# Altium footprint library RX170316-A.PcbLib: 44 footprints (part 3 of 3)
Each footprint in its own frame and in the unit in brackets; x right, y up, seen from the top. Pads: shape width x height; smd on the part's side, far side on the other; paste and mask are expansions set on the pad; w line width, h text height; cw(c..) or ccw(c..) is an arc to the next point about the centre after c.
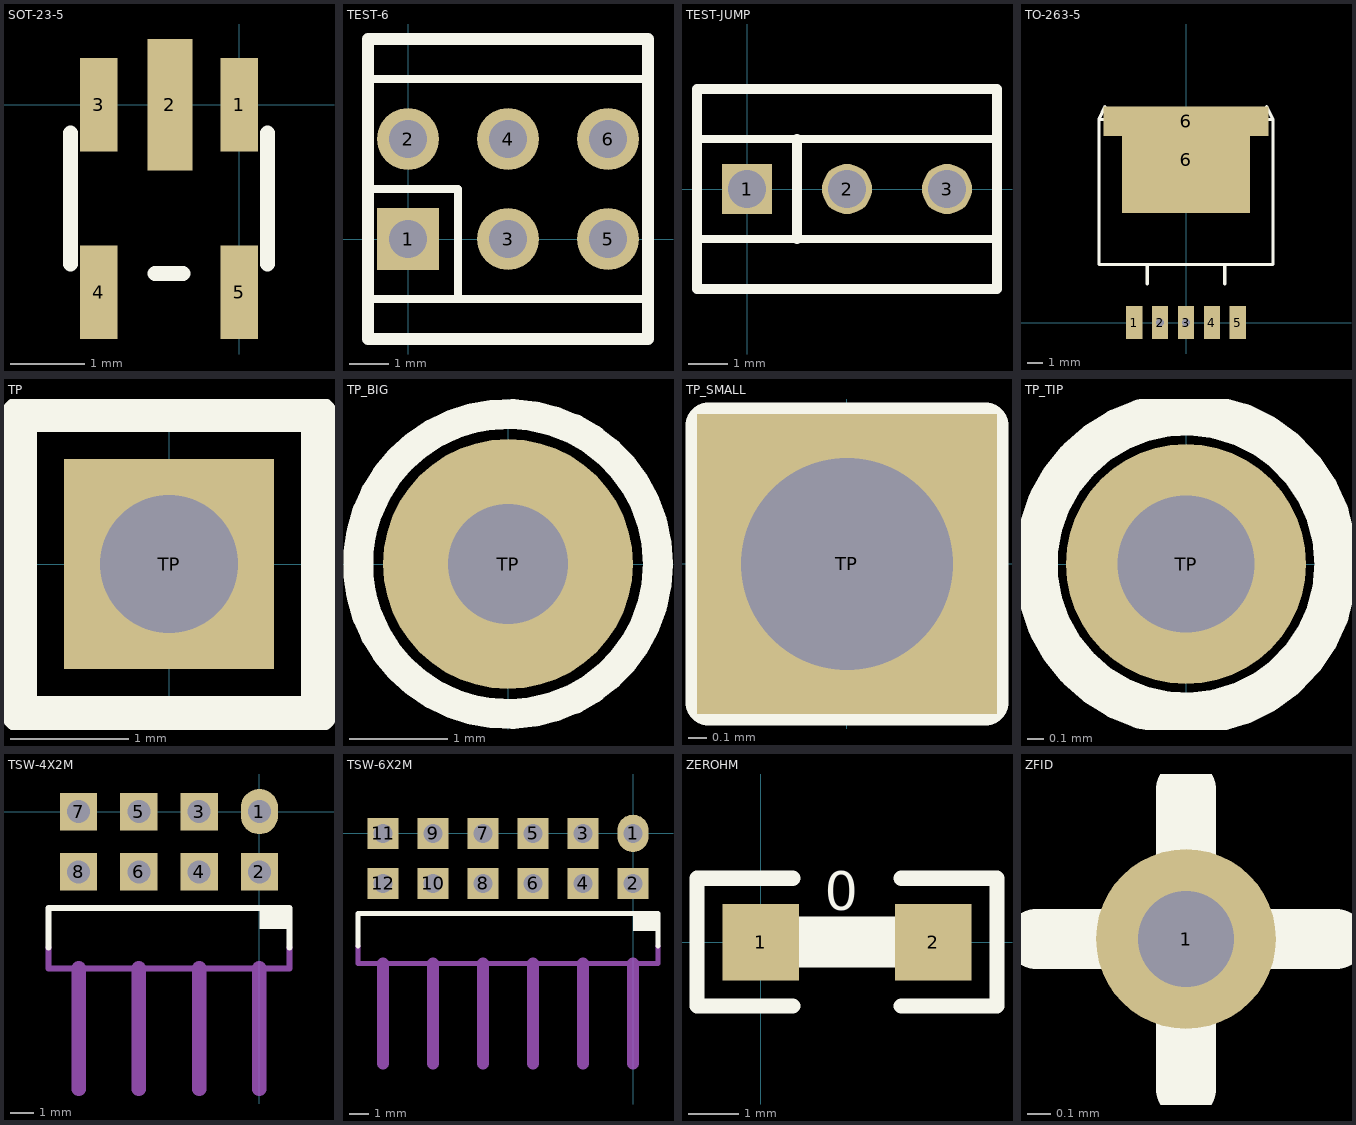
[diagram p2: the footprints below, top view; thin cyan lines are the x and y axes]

## SOT-23-5 [mil]
pads (5):
  rect 20x50 smd mask+5: 1(0,0) 3(-75,0) 4(-75,-100) 5(0,-100)
  rect 24x70 smd mask+5: 2(-37,0)
Top Overlay:
  lines w8: -90,-85 -90,-15 ; -45,-90 -30,-90 ; 15,-85 15,-15

## TEST-6 [mil]
pads (6):
  rect 62x62 hole 38: 1(0,0)
  round 62 hole 38: 2(0,100) 3(100,0) 4(100,100) 5(200,0) 6(200,100)
Top Overlay:
  lines w8: -40,-60 240,-60 ; -40,50 50,50 50,-60 ; -40,160 240,160
  lines w12: -40,-100 240,-100 240,200 -40,200 -40,-100
Mechanical 3:
  text "609-1331-ND" at -130,35 h40

## TEST-JUMP [mil]
pads (3):
  rect 50x50 hole 38: 1(0,0)
  round 50 hole 38: 2(100,0) 3(200,0)
Top Overlay:
  lines w8: -50,-50 250,-50 ; -50,50 250,50
  lines w10: 50,-50 50,50 ; -50,-100 -50,100 250,100 250,-100 -50,-100

## TO-263-5 [mil]
pads (7):
  rect 42x85 smd: 1(-134,0) 4(67,0) 5(134,0)
  rect 42x85 hole 20: 2(-67,0) 3(0,0)
  rect 330x275 smd: 6(0,420)
  rect 425x75 smd: 6(0,520)
Top Overlay:
  lines w8: -209,558 -225,525 ; -100,100 -100,150 ; 100,100 100,150 ; 208,558 225,525 ; -225,525 -225,150 225,150 225,525 ; -225,525 225,525
Top Paste:
  rectangle: -17,-40 18,40
  rectangle: 115,-40 150,40
  rectangle: 50,-40 85,40
  rectangle: -85,-40 -50,40
  rectangle: -150,-40 -115,40

## TP [mil]
pads (1):
  rect 70x70 hole 46 mask+5: TP(0,0)
Top Overlay:
  lines w12: -50,-50 -50,50 50,50 50,-50 -50,-50

## TP_BIG [mil]
pads (1):
  round 100 hole 48: TP(0,0)
Top Overlay:
  circle w12: c0,0 r60

## TP_SMALL [mil]
pads (1):
  rect 65x65 hole 46 mask+5: TP(0,0)
Top Overlay:
  lines w10: -30,-30 -30,30 30,30 30,-30 -30,-30

## TP_TIP [mil]
pads (1):
  round 56 hole 32 mask+3: TP(0,0)
Top Overlay:
  circle w10: c0,0 r35

## TSW-4X2M [mil]
pads (8):
  oval 62x75 hole 38: 1(0,0)
  rect 62x62 hole 38: 2(0,-100) 3(-100,0) 4(-100,-100) 5(-200,0) 6(-200,-100) 7(-300,0) 8(-300,-100)
Top Overlay:
  region: 0,-155 0,-195 50,-195 50,-155
  lines w10: -350,-225 -350,-160 50,-160 50,-225
Mechanical 1:
  lines w10: -350,-225 -350,-260 50,-260 50,-225
  lines w24: -300,-460 -300,-260 ; -200,-460 -200,-260 ; -100,-460 -100,-260 ; 0,-460 0,-260
  text "TSW-4X2M" at -350,-225 h50

## TSW-6X2M [mil]
pads (12):
  oval 62x75 hole 38: 1(0,0)
  rect 62x62 hole 38: 2(0,-100) 3(-100,0) 4(-100,-100) 5(-200,0) 6(-200,-100) 7(-300,0) 8(-300,-100) 9(-400,0) 10(-400,-100) 11(-500,0) 12(-500,-100)
Top Overlay:
  region: 0,-155 0,-195 50,-195 50,-155
  lines w10: -550,-225 -550,-160 50,-160 50,-225
Mechanical 1:
  lines w10: -550,-225 -550,-260 50,-260 50,-225
  lines w24: -500,-460 -500,-260 ; -400,-460 -400,-260 ; -300,-460 -300,-260 ; -200,-460 -200,-260 ; -100,-460 -100,-260 ; 0,-460 0,-260
  text "TSW-6X2M" at -445,-230 h50

## ZEROHM [mil]
pads (2):
  rect 60x60 smd: 1(0,0) 2(135,0)
Top Overlay:
  region: 30,20 30,-20 105,-20 105,20
  lines w12: 25,-50 -50,-50 -50,50 25,50 ; 110,-50 185,-50 185,50 110,50
  text "0" at 50,25 h30

## ZFID [mil]
pads (1):
  round 30 hole 16: 1(0,0)
Top Overlay:
  lines w10: -25,0 0,0 ; 0,-25 0,0 ; 0,25 0,0 ; 25,0 0,0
